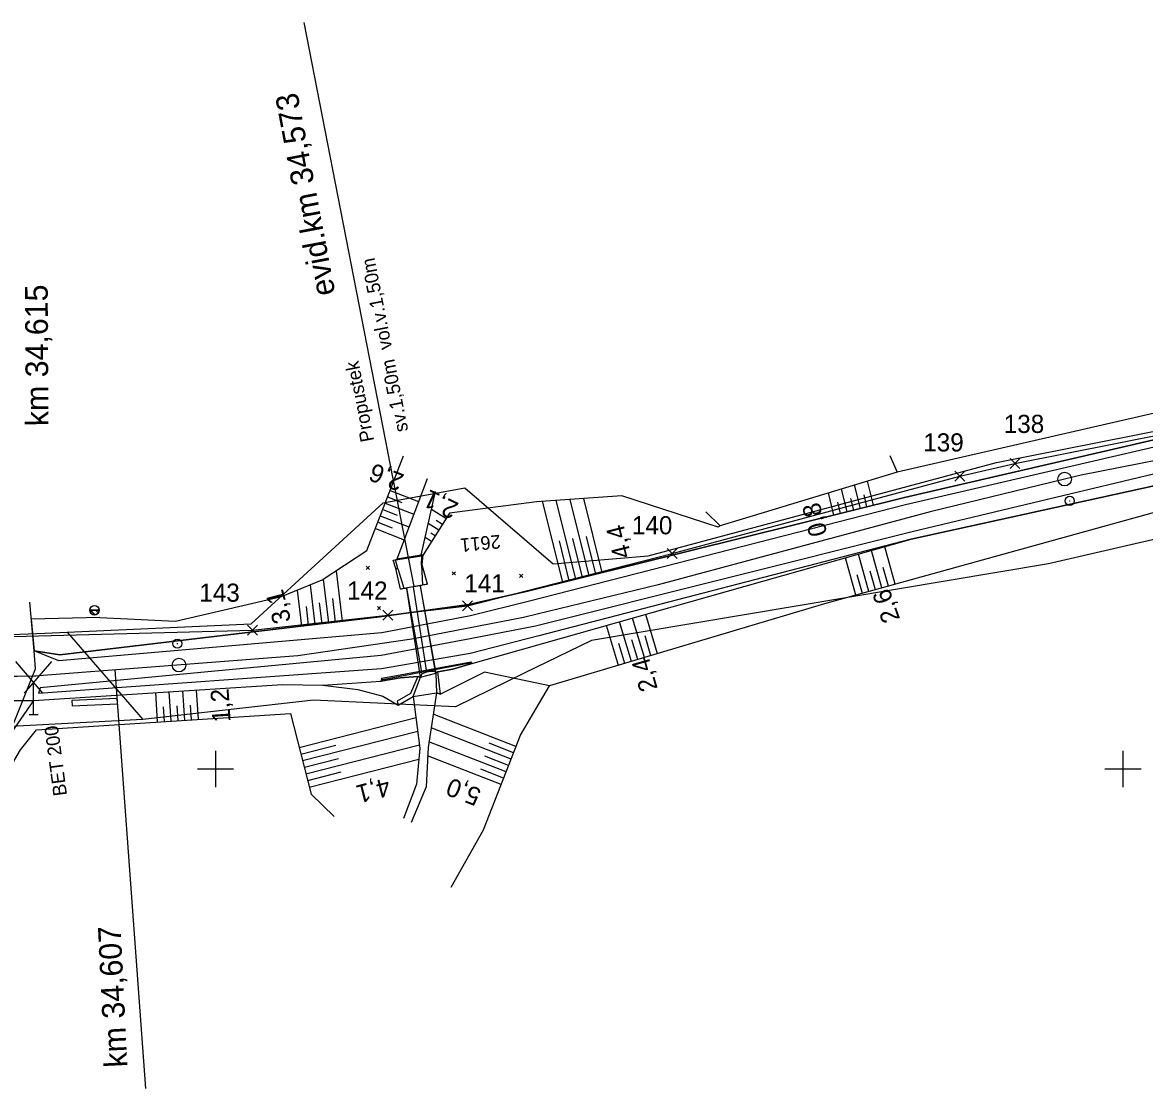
# Model space of a CAD drawing. Extents: x -805730 to -804640, y -1150889 to -1150366.
# Drawn here: x -805421.3 to -805297.6, y -1150735.2 to -1150617.7 of the extents above; entities that cross this region are included whole.
import ezdxf

# ---------------------------------------------------------------- set-up
doc = ezdxf.new("R2010")
doc.units = 0
for name, color, linetype in [('0381KM032-037P - Vrstva 1', 7, 'Continuous'), ('0381KM032-037P - Vrstva 17', 7, 'Continuous'), ('0381KM032-037P - Vrstva 19', 7, 'Continuous'), ('0381KM032-037P - Vrstva 36', 7, 'Continuous'), ('0381KM032-037P - Vrstva 4', 7, 'Continuous'), ('0381KM032-037P - Vrstva 48', 7, 'Continuous'), ('0381KM032-037P - Vrstva 49', 7, 'Continuous'), ('0381KM032-037P - Vrstva 51', 7, 'Continuous'), ('0381KM032-037P - Vrstva 55', 7, 'Continuous'), ('0381KM032-037P - Vrstva 57', 7, 'Continuous'), ('0381KM032-037P - Vrstva 7', 7, 'Continuous'), ('0381KM032-037P - Vrstva 9', 7, 'Continuous'), ('Default', 7, 'Continuous'), ('hran DP - hran DP', 7, 'Continuous'), ('krizky_1000 - Vrstva 1', 7, 'Continuous'), ('PSR_C2_2_Lomove_body_Vimperk - Vrstva 60', 7, 'Continuous'), ('PSR_C2_2_trasa_Vimperk - Kabelová trasa', 7, 'Continuous')]:
    doc.layers.add(name, color=color, linetype=linetype)

msp = doc.modelspace()

# ---------------------------------------------------------------- linework, layer by layer
at = {"layer": '0381KM032-037P - Vrstva 1'}
for points in [[(-805262.34, -1150660.99), (-805275.34, -1150662.5), (-805288.75, -1150664.54), (-805289.64, -1150664.68), (-805304.6, -1150667.62), (-805306.42, -1150668.06)], [(-805306.42, -1150668.06), (-805321.24, -1150671.67), (-805334.8, -1150675.29), (-805351.21, -1150679.7), (-805364.56, -1150682.93)], [(-805364.56, -1150682.93), (-805366.04, -1150683.29), (-805378.36, -1150685.71), (-805390.91, -1150687.55), (-805419.96, -1150689.78), (-805423.96, -1150689.8), (-805433.29, -1150689.8), (-805447.38, -1150689.21), (-805460.61, -1150688.07), (-805473.24, -1150686.41), (-805486.12, -1150684.11), (-805496.07, -1150681.84)]]:
    msp.add_lwpolyline(points, dxfattribs=at)
at = {"layer": '0381KM032-037P - Vrstva 17'}
msp.add_lwpolyline([(-805325.7, -1150665.45), (-805324.89, -1150667.28), (-805344.39, -1150673.21), (-805345.97, -1150671.67)], dxfattribs=at)
at = {"layer": '0381KM032-037P - Vrstva 19'}
for p, q in [((-805378.12, -1150679.9), (-805390.23, -1150617.73)), ((-805380.17, -1150676.97), (-805377.25, -1150676.53)), ((-805377.12, -1150676.41), (-805377.25, -1150676.53)), ((-805377.23, -1150677.51), (-805377.12, -1150676.41)), ((-805380.42, -1150677), (-805380.17, -1150676.97)), ((-805380.12, -1150677.92), (-805380.42, -1150677)), ((-805378.95, -1150680.08), (-805377.25, -1150689.53)), ((-805377.4, -1150689.87), (-805378.93, -1150680.13)), ((-805378.22, -1150679.93), (-805376.73, -1150689.34)), ((-805377.44, -1150679.8), (-805375.79, -1150689.3)), ((-805377.44, -1150679.84), (-805375.71, -1150689.44)), ((-805371.83, -1150688.19), (-805372.13, -1150688.5)), ((-805381.67, -1150690), (-805381.78, -1150690.33)), ((-805425.41, -1150692.47), (-805420.07, -1150692.47)), ((-805378.2, -1150692.01), (-805375.64, -1150691.6))]:
    msp.add_line(p, q, dxfattribs=at)
for points in [[(-805379.92, -1150677.91), (-805380.17, -1150676.97), (-805380.03, -1150676.88), (-805377.35, -1150676.44)], [(-805377.3, -1150677.55), (-805377.25, -1150676.53), (-805377.35, -1150676.44)], [(-805377.44, -1150679.8), (-805377.44, -1150679.84), (-805377.2, -1150679.71), (-805376.64, -1150679.64), (-805377.23, -1150677.51), (-805377.3, -1150677.55), (-805377.2, -1150679.71)], [(-805379.6, -1150680.17), (-805380.12, -1150677.92), (-805379.92, -1150677.91), (-805379.23, -1150680.09)], [(-805376.64, -1150679.64), (-805379.6, -1150680.17), (-805379.23, -1150680.09), (-805378.93, -1150680.13), (-805378.95, -1150680.08)], [(-805377.25, -1150689.53), (-805377.4, -1150689.87), (-805377.71, -1150689.8), (-805379.64, -1150689.94), (-805381.78, -1150690.33), (-805381.61, -1150690.16), (-805381.67, -1150690), (-805371.83, -1150688.19), (-805371.8, -1150688.29), (-805381.61, -1150690.16)], [(-805371.8, -1150688.29), (-805372.13, -1150688.5), (-805373.84, -1150688.99), (-805375.5, -1150689.3), (-805375.71, -1150689.44), (-805375.79, -1150689.3)], [(-805377.71, -1150689.8), (-805378.52, -1150691.68), (-805379.98, -1150692.52), (-805379.86, -1150692.97), (-805378.2, -1150692.01), (-805377.4, -1150689.87)], [(-805375.71, -1150689.44), (-805375.64, -1150691.6), (-805375.2, -1150691.74), (-805375.5, -1150689.3)]]:
    msp.add_lwpolyline(points, dxfattribs=at)
for centre, major_axis, ratio, start_param, end_param in [((-805378.2, -1150679.95), (-0.792, -0.149), 0.032025, 3.416243, 5.97224), ((-805376.52, -1150689.46), (-0.761, -0.129), 0.198559, 3.38498, 5.924926)]:
    msp.add_ellipse(centre, major_axis=major_axis, ratio=ratio, start_param=start_param, end_param=end_param, dxfattribs=at)
at = {"layer": '0381KM032-037P - Vrstva 36'}
for p, q in [((-805413.84, -1150682.5), (-805412.84, -1150682.5)), ((-805412.84, -1150682.5), (-805413.84, -1150682.5)), ((-805413.28, -1150683), (-805413.77, -1150682.5)), ((-805412.94, -1150682.8), (-805413.24, -1150682.5))]:
    msp.add_line(p, q, dxfattribs=at)
msp.add_circle((-805413.34, -1150682.5), 0.503, dxfattribs=at)
msp.add_arc((-805413.34, -1150682.5), 0.503, 180, 0, dxfattribs=at)
at = {"layer": '0381KM032-037P - Vrstva 4'}
for p, q in [((-805422.05, -1150688.15), (-805419.05, -1150691.65)), ((-805421.05, -1150691.65), (-805418.05, -1150688.15)), ((-805423.96, -1150689.8), (-805419.82, -1150689.74)), ((-805420.05, -1150694), (-805420.05, -1150690.5)), ((-805420.55, -1150694), (-805419.55, -1150694))]:
    msp.add_line(p, q, dxfattribs=at)
for points in [[(-805228.99, -1150656.61), (-805257.13, -1150657.62), (-805260.23, -1150658.03), (-805264.49, -1150659.11), (-805283.86, -1150661.58), (-805295.64, -1150663.5), (-805324.06, -1150670.09), (-805365.63, -1150680.4), (-805372.09, -1150681.89), (-805381.91, -1150683.24), (-805417.14, -1150687.42), (-805420, -1150686.97)], [(-805212.28, -1150657.22), (-805228.89, -1150657.63), (-805258.88, -1150659.27), (-805264.46, -1150659.8), (-805283.61, -1150662.28), (-805295.6, -1150664.3), (-805323.97, -1150670.91), (-805365.39, -1150681.52), (-805371.9, -1150683.14), (-805381.67, -1150685.01), (-805417.27, -1150688.09), (-805420, -1150686.97)], [(-805212.01, -1150660.08), (-805229.13, -1150661), (-805258.58, -1150662.1), (-805264.18, -1150662.62), (-805283.43, -1150665.36), (-805294.93, -1150667.11), (-805323.21, -1150673.86), (-805364.72, -1150684.28), (-805371.95, -1150685.67), (-805381.73, -1150687.49), (-805401.63, -1150689.36), (-805419.33, -1150691.07), (-805419.49, -1150691.68)], [(-805225.57, -1150661.42), (-805229.16, -1150661.68), (-805258.55, -1150662.93), (-805264.16, -1150663.27), (-805283.37, -1150665.88), (-805323.33, -1150674.68), (-805364.37, -1150685.33), (-805371.95, -1150687.26), (-805381.71, -1150688.97), (-805419.49, -1150691.68)]]:
    msp.add_lwpolyline(points, dxfattribs=at)
at = {"layer": '0381KM032-037P - Vrstva 48'}
for p, q in [((-805330.39, -1150671.66), (-805331.01, -1150669.14)), ((-805328.93, -1150671.3), (-805329.57, -1150668.7)), ((-805327.47, -1150670.94), (-805328.14, -1150668.27)), ((-805381.03, -1150670.01), (-805379.45, -1150670.62)), ((-805380.75, -1150669.31), (-805377.62, -1150670.53)), ((-805360.28, -1150679.07), (-805362.44, -1150670.39)), ((-805358.83, -1150678.71), (-805360.92, -1150670.29)), ((-805357.37, -1150678.35), (-805359.4, -1150670.18)), ((-805331.84, -1150672.02), (-805332.45, -1150669.58)), ((-805329.66, -1150671.48), (-805329.97, -1150670.2)), ((-805328.2, -1150671.12), (-805328.53, -1150669.8)), ((-805381.57, -1150671.41), (-805379.99, -1150672.02)), ((-805381.3, -1150670.71), (-805378.15, -1150671.93)), ((-805374.6, -1150672.41), (-805376.2, -1150671.41)), ((-805361.74, -1150679.43), (-805363.95, -1150670.5)), ((-805331.11, -1150671.84), (-805331.42, -1150670.6)), ((-805382.11, -1150672.81), (-805380.53, -1150673.42)), ((-805381.84, -1150672.11), (-805378.68, -1150673.33)), ((-805375, -1150673.05), (-805375.68, -1150672.61)), ((-805382.38, -1150673.51), (-805379.21, -1150674.74)), ((-805375.4, -1150673.68), (-805376.55, -1150672.96)), ((-805375.8, -1150674.31), (-805376.26, -1150674.02)), ((-805376.2, -1150674.95), (-805376.9, -1150674.5)), ((-805361.01, -1150679.25), (-805362.1, -1150674.85)), ((-805359.56, -1150678.89), (-805360.62, -1150674.62)), ((-805358.1, -1150678.53), (-805359.13, -1150674.38)), ((-805327.99, -1150680.45), (-805329.14, -1150676.32)), ((-805326.55, -1150680.05), (-805327.69, -1150675.91)), ((-805325.1, -1150679.65), (-805326.25, -1150675.51)), ((-805329.44, -1150680.85), (-805330.58, -1150676.73)), ((-805325.82, -1150679.85), (-805326.4, -1150677.78)), ((-805387.51, -1150683.91), (-805388.09, -1150679.07)), ((-805386.02, -1150683.73), (-805386.68, -1150678.15)), ((-805328.71, -1150680.65), (-805329.29, -1150678.59)), ((-805327.27, -1150680.25), (-805327.84, -1150678.19)), ((-805390.49, -1150684.26), (-805390.96, -1150680.28)), ((-805389, -1150684.08), (-805389.52, -1150679.69)), ((-805386.77, -1150683.82), (-805387.08, -1150681.21)), ((-805389.75, -1150684.17), (-805389.99, -1150682.08)), ((-805388.26, -1150684), (-805388.53, -1150681.7)), ((-805354.17, -1150688.16), (-805355.47, -1150683.78)), ((-805352.73, -1150687.73), (-805354.03, -1150683.37)), ((-805351.29, -1150687.3), (-805352.58, -1150682.96)), ((-805355.6, -1150688.59), (-805356.92, -1150684.19)), ((-805354.89, -1150688.37), (-805355.54, -1150686.18)), ((-805353.45, -1150687.94), (-805354.1, -1150685.76)), ((-805352.01, -1150687.52), (-805352.66, -1150685.34)), ((-805403.39, -1150694.62), (-805403.59, -1150691.39)), ((-805401.89, -1150694.52), (-805402.09, -1150691.3)), ((-805406.38, -1150694.81), (-805406.59, -1150691.59)), ((-805404.88, -1150694.71), (-805405.09, -1150691.49)), ((-805405.63, -1150694.76), (-805405.73, -1150693.15)), ((-805404.13, -1150694.66), (-805404.24, -1150693.05)), ((-805402.64, -1150694.57), (-805402.74, -1150692.96)), ((-805390.77, -1150697.63), (-805377.9, -1150694.34)), ((-805366.89, -1150697.51), (-805376.01, -1150693.96)), ((-805390.4, -1150699.08), (-805377.71, -1150695.84)), ((-805367.43, -1150698.91), (-805376.24, -1150695.48)), ((-805390.59, -1150698.36), (-805386.75, -1150697.38)), ((-805390.03, -1150700.54), (-805377.53, -1150697.34)), ((-805367.98, -1150700.31), (-805376.48, -1150697)), ((-805367.16, -1150698.21), (-805369.85, -1150697.16)), ((-805390.21, -1150699.81), (-805386.44, -1150698.85)), ((-805368.52, -1150701.71), (-805376.62, -1150698.55)), ((-805367.71, -1150699.61), (-805370.3, -1150698.6)), ((-805389.66, -1150701.99), (-805377.59, -1150698.91)), ((-805368.25, -1150701.01), (-805370.75, -1150700.03)), ((-805389.84, -1150701.27), (-805386.15, -1150700.32))]:
    msp.add_line(p, q, dxfattribs=at)
at = {"layer": '0381KM032-037P - Vrstva 49'}
for p, q in [((-805383.32, -1150675.93), (-805379.28, -1150665.5)), ((-805376.67, -1150668.04), (-805380.03, -1150676.88)), ((-805377.35, -1150676.44), (-805375.74, -1150669.42)), ((-805374.21, -1150671.8), (-805377.12, -1150676.41)), ((-805377.35, -1150676.44), (-805380.03, -1150676.88)), ((-805377.12, -1150676.41), (-805377.35, -1150676.44)), ((-805383.03, -1150677.64), (-805383.38, -1150678)), ((-805383.38, -1150677.64), (-805383.02, -1150678)), ((-805373.92, -1150678.26), (-805373.56, -1150678.61)), ((-805373.56, -1150678.26), (-805373.91, -1150678.61)), ((-805366.14, -1150678.54), (-805366.49, -1150678.89)), ((-805366.49, -1150678.54), (-805366.13, -1150678.89)), ((-805381.8, -1150682.09), (-805382.15, -1150682.45)), ((-805382.15, -1150682.09), (-805381.8, -1150682.44))]:
    msp.add_line(p, q, dxfattribs=at)
for points in [[(-805420, -1150686.97), (-805417.14, -1150687.42), (-805381.91, -1150683.24), (-805372.09, -1150681.89), (-805365.63, -1150680.4), (-805324.06, -1150670.09), (-805295.64, -1150663.5), (-805283.86, -1150661.58), (-805264.49, -1150659.11)], [(-805372.13, -1150688.5), (-805323.33, -1150674.68), (-805283.37, -1150665.88), (-805264.16, -1150663.27), (-805258.55, -1150662.93), (-805229.16, -1150661.68), (-805225.47, -1150661.83)], [(-805296.52, -1150660.78), (-805324.89, -1150667.28), (-805344.39, -1150673.21)], [(-805229.52, -1150663.36), (-805258.94, -1150664.75), (-805264.69, -1150666.1), (-805283.13, -1150668.03), (-805332.88, -1150681.81), (-805363.18, -1150690.85)], [(-805344.39, -1150673.21), (-805344.61, -1150673.34), (-805355.22, -1150669.89), (-805364.63, -1150670.55), (-805374.21, -1150671.8)], [(-805412.74, -1150683.31), (-805404.41, -1150683.71), (-805392.74, -1150681.01), (-805388.23, -1150679.16), (-805383.32, -1150675.93)], [(-805412.74, -1150683.31), (-805420.31, -1150683.48), (-805420, -1150686.97)], [(-805420.07, -1150692.47), (-805392.63, -1150690.68), (-805388.18, -1150690.75), (-805381.78, -1150690.33), (-805379.64, -1150689.94), (-805377.71, -1150689.8), (-805377.4, -1150689.87), (-805375.71, -1150689.44), (-805375.5, -1150689.3), (-805373.84, -1150688.99), (-805372.13, -1150688.5)], [(-805363.18, -1150690.85), (-805370.35, -1150689.33), (-805375.2, -1150691.74), (-805375.64, -1150691.6)], [(-805388.18, -1150690.75), (-805384.32, -1150691.25), (-805381.55, -1150691.98), (-805379.86, -1150692.97), (-805378.2, -1150692.01), (-805377.48, -1150697.71), (-805377.85, -1150701.68), (-805379.27, -1150705.45)], [(-805374.03, -1150713.04), (-805370.47, -1150706.7), (-805366.4, -1150696.26), (-805363.18, -1150690.85)], [(-805420.07, -1150692.47), (-805422.84, -1150696.5), (-805425.52, -1150700.88)], [(-805378.2, -1150692.01), (-805375.64, -1150691.6), (-805376.57, -1150697.62), (-805376.78, -1150701.96), (-805378.44, -1150705.91)], [(-805419.74, -1150695.67), (-805391.73, -1150693.87), (-805389.46, -1150702.77), (-805386.92, -1150705.25)], [(-805423.96, -1150702.03), (-805421.5, -1150697.89), (-805419.74, -1150695.67)]]:
    msp.add_lwpolyline(points, dxfattribs=at)
at = {"layer": '0381KM032-037P - Vrstva 51'}
msp.add_lwpolyline([(-805425.52, -1150700.88), (-805422.84, -1150696.5), (-805419.83, -1150688.97), (-805420, -1150686.97), (-805420.48, -1150681.6)], dxfattribs=at)
at = {"layer": '0381KM032-037P - Vrstva 55'}
msp.add_line((-805416.34, -1150684.94), (-805408.01, -1150694.56), dxfattribs=at)
at = {"layer": '0381KM032-037P - Vrstva 7'}
for p, q in [((-805305.9, -1150670.45), (-805305.8, -1150670.45)), ((-805404.26, -1150686.19), (-805404.16, -1150686.19))]:
    msp.add_line(p, q, dxfattribs=at)
for centre, radius in [((-805306.42, -1150668.06), 0.75), ((-805305.85, -1150670.45), 0.5), ((-805404.21, -1150686.19), 0.5), ((-805404.03, -1150688.55), 0.75)]:
    msp.add_circle(centre, radius, dxfattribs=at)
at = {"layer": '0381KM032-037P - Vrstva 9'}
for p, q in [((-805411.08, -1150689.08), (-805407.73, -1150735.22)), ((-805410.84, -1150692.23), (-805415.83, -1150692.47)), ((-805415.83, -1150692.47), (-805415.8, -1150693.06)), ((-805410.84, -1150692.23), (-805410.86, -1150691.64)), ((-805410.81, -1150692.82), (-805410.84, -1150692.23)), ((-805415.8, -1150693.06), (-805410.81, -1150692.82))]:
    msp.add_line(p, q, dxfattribs=at)
at = {"layer": 'hran DP - hran DP'}
for p, q in [((-805313.93, -1150666.21), (-805288.99, -1150661.29)), ((-805352.32, -1150676.52), (-805313.93, -1150666.21)), ((-805267.02, -1150667.87), (-805308.19, -1150677.39)), ((-805381.52, -1150670.67), (-805372.51, -1150669.03)), ((-805372.51, -1150669.03), (-805362.8, -1150677.38)), ((-805396.07, -1150684.02), (-805381.52, -1150670.67)), ((-805362.8, -1150677.38), (-805352.32, -1150676.52)), ((-805308.19, -1150677.39), (-805358.57, -1150685.85)), ((-805416.34, -1150684.94), (-805396.07, -1150684.02)), ((-805423.42, -1150685.2), (-805418.81, -1150685.03)), ((-805418.81, -1150685.03), (-805416.34, -1150684.94)), ((-805358.57, -1150685.85), (-805365.99, -1150689.46)), ((-805365.99, -1150689.46), (-805373.55, -1150693.14)), ((-805389.21, -1150692.42), (-805408.01, -1150694.56)), ((-805373.55, -1150693.14), (-805389.21, -1150692.42)), ((-805408.01, -1150694.56), (-805420.42, -1150695.2)), ((-805420.42, -1150695.2), (-805426.08, -1150695.49))]:
    msp.add_line(p, q, dxfattribs=at)
at = {"layer": 'krizky_1000 - Vrstva 1'}
for points in [[(-805400, -1150698), (-805400, -1150702)], [(-805300, -1150698), (-805300, -1150702)], [(-805402, -1150700), (-805398, -1150700)], [(-805302, -1150700), (-805298, -1150700)]]:
    msp.add_lwpolyline(points, dxfattribs=at)
at = {"layer": 'PSR_C2_2_Lomove_body_Vimperk - Vrstva 60'}
for p, q in [((-805312.44, -1150666.88), (-805311.34, -1150665.78)), ((-805311.34, -1150666.88), (-805312.44, -1150665.78)), ((-805318.53, -1150668.3), (-805317.43, -1150667.2)), ((-805317.43, -1150668.3), (-805318.53, -1150667.2)), ((-805350.23, -1150676.82), (-805349.13, -1150675.72)), ((-805349.13, -1150676.82), (-805350.23, -1150675.72)), ((-805372.77, -1150682.58), (-805371.67, -1150681.48)), ((-805371.67, -1150682.58), (-805372.77, -1150681.48)), ((-805381.56, -1150683.59), (-805380.46, -1150682.49)), ((-805380.46, -1150683.59), (-805381.56, -1150682.49)), ((-805396.46, -1150685.26), (-805395.36, -1150684.16)), ((-805395.36, -1150685.26), (-805396.46, -1150684.16))]:
    msp.add_line(p, q, dxfattribs=at)
at = {"layer": 'PSR_C2_2_trasa_Vimperk - Kabelová trasa'}
for points in [[(-805372.22, -1150682.03), (-805349.68, -1150676.27), (-805317.98, -1150667.75), (-805311.89, -1150666.33), (-805283.81, -1150660.76), (-805266.17, -1150658.11), (-805251.29, -1150654.49), (-805239.52, -1150653.99)], [(-805422.27, -1150685.42), (-805395.91, -1150684.71), (-805381.01, -1150683.04), (-805372.22, -1150682.03)]]:
    msp.add_lwpolyline(points, dxfattribs=at)

# ---------------------------------------------------------------- texts
at = {"layer": '0381KM032-037P - Vrstva 19'}
for s, height, rotation, p in [('evid.km 34,573', 2.5, 100.6945, (-805386.78, -1150647.62)), ('sv.1,50m  vol.v.1,50m', 1.4999, 101.0532, (-805378.75, -1150662.72)), ('Propustek', 1.5, 101.1547, (-805382.51, -1150663.81)), ('BET 200', 1.5, 97.5063, (-805416.36, -1150702.88))]:
    msp.add_text(s, height=height, rotation=rotation, dxfattribs=at).set_placement(p)
at = {"layer": '0381KM032-037P - Vrstva 4'}
msp.add_text('km 34,615', height=2.5, rotation=90.3142, dxfattribs=at).set_placement((-805418.41, -1150662.22))
at = {"layer": '0381KM032-037P - Vrstva 48'}
for s, height, rotation, p in [('2,6', 2, 158.8025, (-805379.08, -1150667.6)), ('2,1', 2, 154.4647, (-805373.08, -1150670.75)), ('0,8', 1.99, 103.9155, (-805332.56, -1150674.1)), ('4,4', 2, 103.9188, (-805354.16, -1150676.55)), ('3,1', 2, 104.8055, (-805391.65, -1150683.68)), ('2,6', 2, 109.5492, (-805324.53, -1150683.48)), ('2,4', 2, 105.8138, (-805351.25, -1150691.15)), ('1,2', 2, 93.6817, (-805398.33, -1150694.8)), ('4,1', 2, 194.3297, (-805381.04, -1150700.95)), ('5,0', 2, 158.7077, (-805370.58, -1150702.28))]:
    msp.add_text(s, height=height, rotation=rotation, dxfattribs=at).set_placement(p)
at = {"layer": '0381KM032-037P - Vrstva 57'}
msp.add_text('2611', height=1.5, rotation=185.7179, dxfattribs=at).set_placement((-805368.65, -1150674.18))
at = {"layer": '0381KM032-037P - Vrstva 9'}
msp.add_text('km 34,607', height=2.5, rotation=92.7706, dxfattribs=at).set_placement((-805409.71, -1150732.84))
at = {"layer": 'Default'}
for s, p in [('138', (-805313.13, -1150662.97)), ('139', (-805322, -1150665.01)), ('140', (-805354.11, -1150674.14)), ('141', (-805372.58, -1150680.54)), ('143', (-805401.79, -1150681.57)), ('142', (-805385.5, -1150681.34))]:
    msp.add_text(s, height=2, dxfattribs=at).set_placement(p)

doc.saveas('drawing.dxf')
